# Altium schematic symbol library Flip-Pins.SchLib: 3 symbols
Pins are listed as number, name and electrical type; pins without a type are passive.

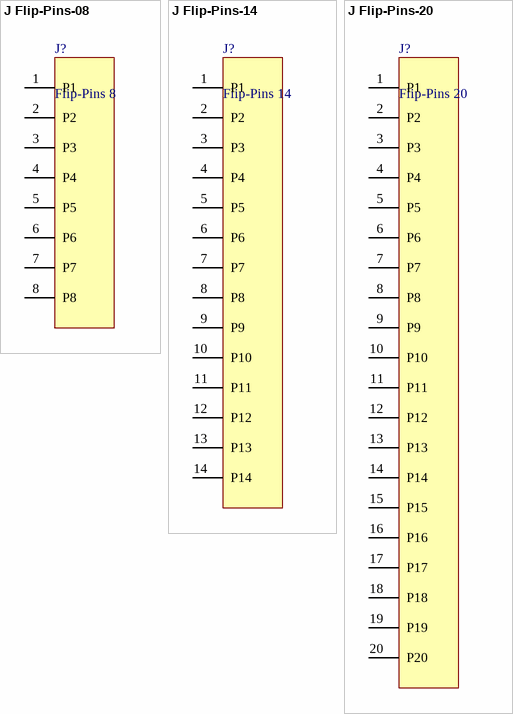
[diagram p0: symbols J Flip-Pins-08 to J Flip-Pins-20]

## J Flip-Pins-08
designator J?, comment Flip-Pins 8
footprint Flip-Pins-08 (Flip-Pins 8 pins)
footprint Flip-Pins-08_Aligner (Flip-Pins 8 pins with Aligner)
pins: 1 P1, 2 P2, 3 P3, 4 P4, 5 P5, 6 P6, 7 P7, 8 P8

## J Flip-Pins-14
designator J?, comment Flip-Pins 14
footprint Flip-Pins-14 (Flip-Pins 14 pins)
footprint Flip-Pins-14_Aligner (Flip-Pins 14 pins with Aligner)
pins: 1 P1, 2 P2, 3 P3, 4 P4, 5 P5, 6 P6, 7 P7, 8 P8, 9 P9, 10 P10, 11 P11, 12 P12, 13 P13, 14 P14

## J Flip-Pins-20
designator J?, comment Flip-Pins 20
footprint Flip-Pins-20 (Flip-Pins 20 pins)
footprint Flip-Pins-20_Aligner (Flip-Pins 20 pins with Aligner)
pins: 1 P1, 2 P2, 3 P3, 4 P4, 5 P5, 6 P6, 7 P7, 8 P8, 9 P9, 10 P10, 11 P11, 12 P12, 13 P13, 14 P14, 15 P15, 16 P16, 17 P17, 18 P18, 19 P19, 20 P20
